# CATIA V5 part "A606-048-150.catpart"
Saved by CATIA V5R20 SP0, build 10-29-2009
Part number: A606-048-150
Source: Unknown
Property "ARTICLENO": "A606-048-150"
Property "BOMINFO": "A606-048-150"
Property "CODE": "A606-048-150"
Property "HOLES": "2"
Property "L": "150.000"
Property "L1": "25.000"
Property "L2": "100.000"
Property "LINA": "A606-048-150"
Property "NB": "A606-048-150"
Property "NBSYN": "$CODE."
Property "NN": "A606"
Property "NT": "Wear Plates, self-lubricating"
Property "SCREW": "2xM6"
Property "SUPPLIER": "CF"
Property "W": "48.000"
Bounding box of the stored display mesh (mm): x -24 to 24, y -5 to 5, z -75 to 75
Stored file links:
  C:\Users\Utente\Desktop\3D files A606\A606-048-150.catpart
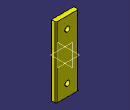
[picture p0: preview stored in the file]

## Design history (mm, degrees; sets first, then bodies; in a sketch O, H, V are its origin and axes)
Body1 "Geometry.1" (main body)
  Solid1 "A606-048-150.catpart": solid without history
